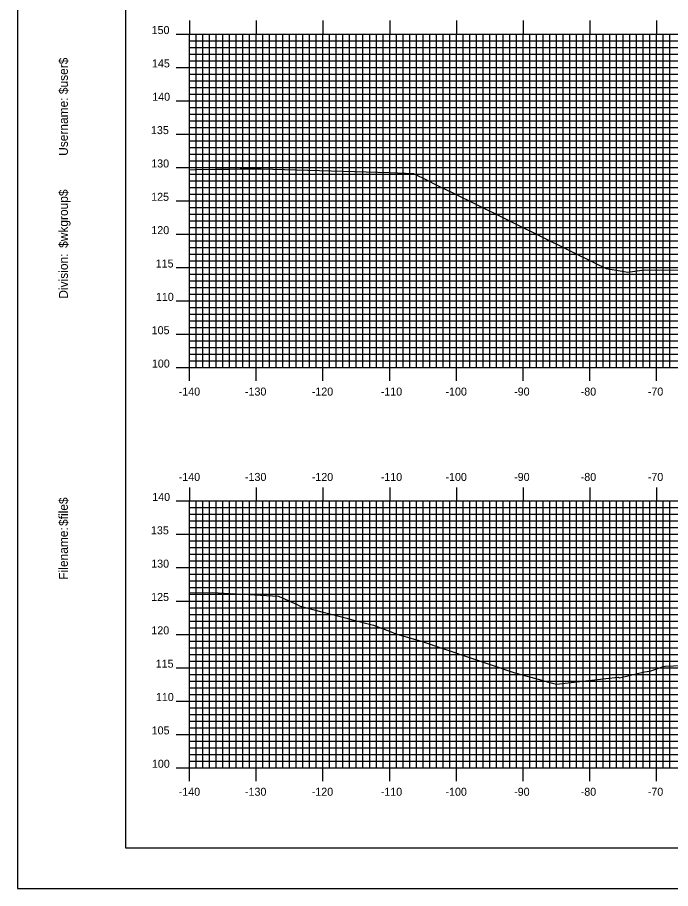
# Model space of a CAD drawing. Extents: x 1684799 to 1685142, y 461260 to 461480.
# Drawn here: x 1684798.9 to 1684896.8, y 461260 to 461390.6 of the extents above; entities that cross this region are included whole.
import ezdxf

# ---------------------------------------------------------------- set-up
doc = ezdxf.new("R2010")
doc.units = 0
for name, color, linetype in [('BORDER', 7, 'Continuous'), ('H_V ANNOTATION', 7, 'Continuous'), ('MAJOR', 7, 'Continuous'), ('MINOR', 7, 'Continuous'), ('PLOT BOUNDARY', 7, 'Continuous'), ('S_Roadway_Centerline', 7, 'Continuous')]:
    doc.layers.add(name, color=color, linetype=linetype)

msp = doc.modelspace()

# ---------------------------------------------------------------- linework, layer by layer
at = {"layer": 'BORDER'}
msp.add_lwpolyline([(1684815.12, 461266.07), (1685135.12, 461266.07), (1685135.12, 461476.07), (1684815.12, 461476.07)], close=True, dxfattribs=at)
at = {"layer": 'MAJOR'}
for p, q in [((1684824.72, 461390.08), (1684824.72, 461388.07)), ((1684834.72, 461390.08), (1684834.72, 461388.07)), ((1684844.72, 461390.08), (1684844.72, 461388.07)), ((1684854.72, 461390.08), (1684854.72, 461388.07)), ((1684864.72, 461390.08), (1684864.72, 461388.07)), ((1684874.72, 461390.08), (1684874.72, 461388.07)), ((1684884.72, 461390.08), (1684884.72, 461388.07)), ((1684894.72, 461390.08), (1684894.72, 461388.07)), ((1684822.71, 461388.07), (1684824.72, 461388.07)), ((1684824.72, 461388.07), (1685104.72, 461388.07)), ((1684824.72, 461338.07), (1684824.72, 461388.07)), ((1684824.72, 461338.07), (1684824.72, 461388.07)), ((1684824.72, 461388.07), (1685104.72, 461388.07)), ((1684834.72, 461338.07), (1684834.72, 461388.07)), ((1684844.72, 461338.07), (1684844.72, 461388.07)), ((1684854.72, 461338.07), (1684854.72, 461388.07)), ((1684864.72, 461338.07), (1684864.72, 461388.07)), ((1684874.72, 461338.07), (1684874.72, 461388.07)), ((1684884.72, 461338.07), (1684884.72, 461388.07)), ((1684894.72, 461338.07), (1684894.72, 461388.07)), ((1684822.71, 461383.07), (1684824.72, 461383.07)), ((1684824.72, 461383.07), (1685104.72, 461383.07)), ((1684822.71, 461378.07), (1684824.72, 461378.07)), ((1684824.72, 461378.07), (1685104.72, 461378.07)), ((1684822.71, 461373.07), (1684824.72, 461373.07)), ((1684824.72, 461373.07), (1685104.72, 461373.07)), ((1684822.71, 461368.07), (1684824.72, 461368.07)), ((1684824.72, 461368.07), (1685104.72, 461368.07)), ((1684822.71, 461363.07), (1684824.72, 461363.07)), ((1684824.72, 461363.07), (1685104.72, 461363.07)), ((1684822.71, 461358.07), (1684824.72, 461358.07)), ((1684824.72, 461358.07), (1685104.72, 461358.07)), ((1684822.71, 461353.07), (1684824.72, 461353.07)), ((1684824.72, 461353.07), (1685104.72, 461353.07)), ((1684822.71, 461348.07), (1684824.72, 461348.07)), ((1684824.72, 461348.07), (1685104.72, 461348.07)), ((1684822.71, 461343.07), (1684824.72, 461343.07)), ((1684824.72, 461343.07), (1685104.72, 461343.07)), ((1684822.71, 461338.07), (1684824.72, 461338.07)), ((1684824.72, 461338.07), (1685104.72, 461338.07)), ((1684824.72, 461338.07), (1685104.72, 461338.07)), ((1684824.72, 461336.07), (1684824.72, 461338.07)), ((1684834.72, 461336.07), (1684834.72, 461338.07)), ((1684844.72, 461336.07), (1684844.72, 461338.07)), ((1684854.72, 461336.07), (1684854.72, 461338.07)), ((1684864.72, 461336.07), (1684864.72, 461338.07)), ((1684874.72, 461336.07), (1684874.72, 461338.07)), ((1684884.72, 461336.07), (1684884.72, 461338.07)), ((1684894.72, 461336.07), (1684894.72, 461338.07)), ((1684824.72, 461320.08), (1684824.72, 461318.07)), ((1684834.72, 461320.08), (1684834.72, 461318.07)), ((1684844.72, 461320.08), (1684844.72, 461318.07)), ((1684854.72, 461320.08), (1684854.72, 461318.07)), ((1684864.72, 461320.08), (1684864.72, 461318.07)), ((1684874.72, 461320.08), (1684874.72, 461318.07)), ((1684884.72, 461320.08), (1684884.72, 461318.07)), ((1684894.72, 461320.08), (1684894.72, 461318.07)), ((1684822.71, 461318.07), (1684824.72, 461318.07)), ((1684824.72, 461318.07), (1685104.72, 461318.07)), ((1684824.72, 461278.07), (1684824.72, 461318.07)), ((1684824.72, 461278.07), (1684824.72, 461318.07)), ((1684824.72, 461318.07), (1685104.72, 461318.07)), ((1684834.72, 461278.07), (1684834.72, 461318.07)), ((1684844.72, 461278.07), (1684844.72, 461318.07)), ((1684854.72, 461278.07), (1684854.72, 461318.07)), ((1684864.72, 461278.07), (1684864.72, 461318.07)), ((1684874.72, 461278.07), (1684874.72, 461318.07)), ((1684884.72, 461278.07), (1684884.72, 461318.07)), ((1684894.72, 461278.07), (1684894.72, 461318.07)), ((1684822.71, 461313.07), (1684824.72, 461313.07)), ((1684824.72, 461313.07), (1685104.72, 461313.07)), ((1684822.71, 461308.07), (1684824.72, 461308.07)), ((1684824.72, 461308.07), (1685104.72, 461308.07)), ((1684822.71, 461303.07), (1684824.72, 461303.07)), ((1684824.72, 461303.07), (1685104.72, 461303.07)), ((1684822.71, 461298.07), (1684824.72, 461298.07)), ((1684824.72, 461298.07), (1685104.72, 461298.07)), ((1684822.71, 461293.07), (1684824.72, 461293.07)), ((1684824.72, 461293.07), (1685104.72, 461293.07)), ((1684822.71, 461288.07), (1684824.72, 461288.07)), ((1684824.72, 461288.07), (1685104.72, 461288.07)), ((1684822.71, 461283.07), (1684824.72, 461283.07)), ((1684824.72, 461283.07), (1685104.72, 461283.07)), ((1684822.71, 461278.07), (1684824.72, 461278.07)), ((1684824.72, 461278.07), (1685104.72, 461278.07)), ((1684824.72, 461278.07), (1685104.72, 461278.07)), ((1684824.72, 461276.07), (1684824.72, 461278.07)), ((1684834.72, 461276.07), (1684834.72, 461278.07)), ((1684844.72, 461276.07), (1684844.72, 461278.07)), ((1684854.72, 461276.07), (1684854.72, 461278.07)), ((1684864.72, 461276.07), (1684864.72, 461278.07)), ((1684874.72, 461276.07), (1684874.72, 461278.07)), ((1684884.72, 461276.07), (1684884.72, 461278.07)), ((1684894.72, 461276.07), (1684894.72, 461278.07))]:
    msp.add_line(p, q, dxfattribs=at)
at = {"layer": 'MINOR'}
for p, q in [((1684825.72, 461338.07), (1684825.72, 461388.07)), ((1684826.72, 461338.07), (1684826.72, 461388.07)), ((1684827.72, 461338.07), (1684827.72, 461388.07)), ((1684828.72, 461338.07), (1684828.72, 461388.07)), ((1684829.72, 461338.07), (1684829.72, 461388.07)), ((1684830.72, 461338.07), (1684830.72, 461388.07)), ((1684831.72, 461338.07), (1684831.72, 461388.07)), ((1684832.72, 461338.07), (1684832.72, 461388.07)), ((1684833.72, 461338.07), (1684833.72, 461388.07)), ((1684835.72, 461338.07), (1684835.72, 461388.07)), ((1684836.72, 461338.07), (1684836.72, 461388.07)), ((1684837.72, 461338.07), (1684837.72, 461388.07)), ((1684838.72, 461338.07), (1684838.72, 461388.07)), ((1684839.72, 461338.07), (1684839.72, 461388.07)), ((1684840.72, 461338.07), (1684840.72, 461388.07)), ((1684841.72, 461338.07), (1684841.72, 461388.07)), ((1684842.72, 461338.07), (1684842.72, 461388.07)), ((1684843.72, 461338.07), (1684843.72, 461388.07)), ((1684845.72, 461338.07), (1684845.72, 461388.07)), ((1684846.72, 461338.07), (1684846.72, 461388.07)), ((1684847.72, 461338.07), (1684847.72, 461388.07)), ((1684848.72, 461338.07), (1684848.72, 461388.07)), ((1684849.72, 461338.07), (1684849.72, 461388.07)), ((1684850.72, 461338.07), (1684850.72, 461388.07)), ((1684851.72, 461338.07), (1684851.72, 461388.07)), ((1684852.72, 461338.07), (1684852.72, 461388.07)), ((1684853.72, 461338.07), (1684853.72, 461388.07)), ((1684855.72, 461338.07), (1684855.72, 461388.07)), ((1684856.72, 461338.07), (1684856.72, 461388.07)), ((1684857.72, 461338.07), (1684857.72, 461388.07)), ((1684858.72, 461338.07), (1684858.72, 461388.07)), ((1684859.72, 461338.07), (1684859.72, 461388.07)), ((1684860.72, 461338.07), (1684860.72, 461388.07)), ((1684861.72, 461338.07), (1684861.72, 461388.07)), ((1684862.72, 461338.07), (1684862.72, 461388.07)), ((1684863.72, 461338.07), (1684863.72, 461388.07)), ((1684865.72, 461338.07), (1684865.72, 461388.07)), ((1684866.72, 461338.07), (1684866.72, 461388.07)), ((1684867.72, 461338.07), (1684867.72, 461388.07)), ((1684868.72, 461338.07), (1684868.72, 461388.07)), ((1684869.72, 461338.07), (1684869.72, 461388.07)), ((1684870.72, 461338.07), (1684870.72, 461388.07)), ((1684871.72, 461338.07), (1684871.72, 461388.07)), ((1684872.72, 461338.07), (1684872.72, 461388.07)), ((1684873.72, 461338.07), (1684873.72, 461388.07)), ((1684875.72, 461338.07), (1684875.72, 461388.07)), ((1684876.72, 461338.07), (1684876.72, 461388.07)), ((1684877.72, 461338.07), (1684877.72, 461388.07)), ((1684878.72, 461338.07), (1684878.72, 461388.07)), ((1684879.72, 461338.07), (1684879.72, 461388.07)), ((1684880.72, 461338.07), (1684880.72, 461388.07)), ((1684881.72, 461338.07), (1684881.72, 461388.07)), ((1684882.72, 461338.07), (1684882.72, 461388.07)), ((1684883.72, 461338.07), (1684883.72, 461388.07)), ((1684885.72, 461338.07), (1684885.72, 461388.07)), ((1684886.72, 461338.07), (1684886.72, 461388.07)), ((1684887.72, 461338.07), (1684887.72, 461388.07)), ((1684888.72, 461338.07), (1684888.72, 461388.07)), ((1684889.72, 461338.07), (1684889.72, 461388.07)), ((1684890.72, 461338.07), (1684890.72, 461388.07)), ((1684891.72, 461338.07), (1684891.72, 461388.07)), ((1684892.72, 461338.07), (1684892.72, 461388.07)), ((1684893.72, 461338.07), (1684893.72, 461388.07)), ((1684895.72, 461338.07), (1684895.72, 461388.07)), ((1684896.72, 461338.07), (1684896.72, 461388.07)), ((1684824.72, 461387.07), (1685104.72, 461387.07)), ((1684824.72, 461387.07), (1684826.72, 461387.07)), ((1684824.72, 461386.07), (1685104.72, 461386.07)), ((1684824.72, 461386.07), (1684826.72, 461386.07)), ((1684824.72, 461385.07), (1685104.72, 461385.07)), ((1684824.72, 461385.07), (1684826.72, 461385.07)), ((1684824.72, 461384.07), (1685104.72, 461384.07)), ((1684824.72, 461384.07), (1684826.72, 461384.07)), ((1684824.72, 461382.07), (1685104.72, 461382.07)), ((1684824.72, 461382.07), (1684826.72, 461382.07)), ((1684824.72, 461381.07), (1685104.72, 461381.07)), ((1684824.72, 461381.07), (1684826.72, 461381.07)), ((1684824.72, 461380.07), (1685104.72, 461380.07)), ((1684824.72, 461380.07), (1684826.72, 461380.07)), ((1684824.72, 461379.07), (1685104.72, 461379.07)), ((1684824.72, 461379.07), (1684826.72, 461379.07)), ((1684824.72, 461377.07), (1685104.72, 461377.07)), ((1684824.72, 461377.07), (1684826.72, 461377.07)), ((1684824.72, 461376.07), (1685104.72, 461376.07)), ((1684824.72, 461376.07), (1684826.72, 461376.07)), ((1684824.72, 461375.07), (1685104.72, 461375.07)), ((1684824.72, 461375.07), (1684826.72, 461375.07)), ((1684824.72, 461374.07), (1685104.72, 461374.07)), ((1684824.72, 461374.07), (1684826.72, 461374.07)), ((1684824.72, 461372.07), (1685104.72, 461372.07)), ((1684824.72, 461372.07), (1684826.72, 461372.07)), ((1684824.72, 461371.07), (1685104.72, 461371.07)), ((1684824.72, 461371.07), (1684826.72, 461371.07)), ((1684824.72, 461370.07), (1685104.72, 461370.07)), ((1684824.72, 461370.07), (1684826.72, 461370.07)), ((1684824.72, 461369.07), (1685104.72, 461369.07)), ((1684824.72, 461369.07), (1684826.72, 461369.07)), ((1684824.72, 461367.07), (1685104.72, 461367.07)), ((1684824.72, 461367.07), (1684826.72, 461367.07)), ((1684824.72, 461366.07), (1685104.72, 461366.07)), ((1684824.72, 461366.07), (1684826.72, 461366.07)), ((1684824.72, 461365.07), (1685104.72, 461365.07)), ((1684824.72, 461365.07), (1684826.72, 461365.07)), ((1684824.72, 461364.07), (1685104.72, 461364.07)), ((1684824.72, 461364.07), (1684826.72, 461364.07)), ((1684824.72, 461362.07), (1685104.72, 461362.07)), ((1684824.72, 461362.07), (1684826.72, 461362.07)), ((1684824.72, 461361.07), (1685104.72, 461361.07)), ((1684824.72, 461361.07), (1684826.72, 461361.07)), ((1684824.72, 461360.07), (1685104.72, 461360.07)), ((1684824.72, 461360.07), (1684826.72, 461360.07)), ((1684824.72, 461359.07), (1685104.72, 461359.07)), ((1684824.72, 461359.07), (1684826.72, 461359.07)), ((1684824.72, 461357.07), (1685104.72, 461357.07)), ((1684824.72, 461357.07), (1684826.72, 461357.07)), ((1684824.72, 461356.07), (1685104.72, 461356.07)), ((1684824.72, 461356.07), (1684826.72, 461356.07)), ((1684824.72, 461355.07), (1685104.72, 461355.07)), ((1684824.72, 461355.07), (1684826.72, 461355.07)), ((1684824.72, 461354.07), (1685104.72, 461354.07)), ((1684824.72, 461354.07), (1684826.72, 461354.07)), ((1684824.72, 461352.07), (1685104.72, 461352.07)), ((1684824.72, 461352.07), (1684826.72, 461352.07)), ((1684824.72, 461351.07), (1685104.72, 461351.07)), ((1684824.72, 461351.07), (1684826.72, 461351.07)), ((1684824.72, 461350.07), (1685104.72, 461350.07)), ((1684824.72, 461350.07), (1684826.72, 461350.07)), ((1684824.72, 461349.07), (1685104.72, 461349.07)), ((1684824.72, 461349.07), (1684826.72, 461349.07)), ((1684824.72, 461347.07), (1685104.72, 461347.07)), ((1684824.72, 461347.07), (1684826.72, 461347.07)), ((1684824.72, 461346.07), (1685104.72, 461346.07)), ((1684824.72, 461346.07), (1684826.72, 461346.07)), ((1684824.72, 461345.07), (1685104.72, 461345.07)), ((1684824.72, 461345.07), (1684826.72, 461345.07)), ((1684824.72, 461344.07), (1685104.72, 461344.07)), ((1684824.72, 461344.07), (1684826.72, 461344.07)), ((1684824.72, 461342.07), (1685104.72, 461342.07)), ((1684824.72, 461342.07), (1684826.72, 461342.07)), ((1684824.72, 461341.07), (1685104.72, 461341.07)), ((1684824.72, 461341.07), (1684826.72, 461341.07)), ((1684824.72, 461340.07), (1685104.72, 461340.07)), ((1684824.72, 461340.07), (1684826.72, 461340.07)), ((1684824.72, 461339.07), (1685104.72, 461339.07)), ((1684824.72, 461339.07), (1684826.72, 461339.07)), ((1684824.72, 461317.07), (1685104.72, 461317.07)), ((1684824.72, 461317.07), (1684826.72, 461317.07)), ((1684825.72, 461278.07), (1684825.72, 461318.07)), ((1684826.72, 461278.07), (1684826.72, 461318.07)), ((1684827.72, 461278.07), (1684827.72, 461318.07)), ((1684828.72, 461278.07), (1684828.72, 461318.07)), ((1684829.72, 461278.07), (1684829.72, 461318.07)), ((1684830.72, 461278.07), (1684830.72, 461318.07)), ((1684831.72, 461278.07), (1684831.72, 461318.07)), ((1684832.72, 461278.07), (1684832.72, 461318.07)), ((1684833.72, 461278.07), (1684833.72, 461318.07)), ((1684835.72, 461278.07), (1684835.72, 461318.07)), ((1684836.72, 461278.07), (1684836.72, 461318.07)), ((1684837.72, 461278.07), (1684837.72, 461318.07)), ((1684838.72, 461278.07), (1684838.72, 461318.07)), ((1684839.72, 461278.07), (1684839.72, 461318.07)), ((1684840.72, 461278.07), (1684840.72, 461318.07)), ((1684841.72, 461278.07), (1684841.72, 461318.07)), ((1684842.72, 461278.07), (1684842.72, 461318.07)), ((1684843.72, 461278.07), (1684843.72, 461318.07)), ((1684845.72, 461278.07), (1684845.72, 461318.07)), ((1684846.72, 461278.07), (1684846.72, 461318.07)), ((1684847.72, 461278.07), (1684847.72, 461318.07)), ((1684848.72, 461278.07), (1684848.72, 461318.07)), ((1684849.72, 461278.07), (1684849.72, 461318.07)), ((1684850.72, 461278.07), (1684850.72, 461318.07)), ((1684851.72, 461278.07), (1684851.72, 461318.07)), ((1684852.72, 461278.07), (1684852.72, 461318.07)), ((1684853.72, 461278.07), (1684853.72, 461318.07)), ((1684855.72, 461278.07), (1684855.72, 461318.07)), ((1684856.72, 461278.07), (1684856.72, 461318.07)), ((1684857.72, 461278.07), (1684857.72, 461318.07)), ((1684858.72, 461278.07), (1684858.72, 461318.07)), ((1684859.72, 461278.07), (1684859.72, 461318.07)), ((1684860.72, 461278.07), (1684860.72, 461318.07)), ((1684861.72, 461278.07), (1684861.72, 461318.07)), ((1684862.72, 461278.07), (1684862.72, 461318.07)), ((1684863.72, 461278.07), (1684863.72, 461318.07)), ((1684865.72, 461278.07), (1684865.72, 461318.07)), ((1684866.72, 461278.07), (1684866.72, 461318.07)), ((1684867.72, 461278.07), (1684867.72, 461318.07)), ((1684868.72, 461278.07), (1684868.72, 461318.07)), ((1684869.72, 461278.07), (1684869.72, 461318.07)), ((1684870.72, 461278.07), (1684870.72, 461318.07)), ((1684871.72, 461278.07), (1684871.72, 461318.07)), ((1684872.72, 461278.07), (1684872.72, 461318.07)), ((1684873.72, 461278.07), (1684873.72, 461318.07)), ((1684875.72, 461278.07), (1684875.72, 461318.07)), ((1684876.72, 461278.07), (1684876.72, 461318.07)), ((1684877.72, 461278.07), (1684877.72, 461318.07)), ((1684878.72, 461278.07), (1684878.72, 461318.07)), ((1684879.72, 461278.07), (1684879.72, 461318.07)), ((1684880.72, 461278.07), (1684880.72, 461318.07)), ((1684881.72, 461278.07), (1684881.72, 461318.07)), ((1684882.72, 461278.07), (1684882.72, 461318.07)), ((1684883.72, 461278.07), (1684883.72, 461318.07)), ((1684885.72, 461278.07), (1684885.72, 461318.07)), ((1684886.72, 461278.07), (1684886.72, 461318.07)), ((1684887.72, 461278.07), (1684887.72, 461318.07)), ((1684888.72, 461278.07), (1684888.72, 461318.07)), ((1684889.72, 461278.07), (1684889.72, 461318.07)), ((1684890.72, 461278.07), (1684890.72, 461318.07)), ((1684891.72, 461278.07), (1684891.72, 461318.07)), ((1684892.72, 461278.07), (1684892.72, 461318.07)), ((1684893.72, 461278.07), (1684893.72, 461318.07)), ((1684895.72, 461278.07), (1684895.72, 461318.07)), ((1684896.72, 461278.07), (1684896.72, 461318.07)), ((1684824.72, 461316.07), (1685104.72, 461316.07)), ((1684824.72, 461316.07), (1684826.72, 461316.07)), ((1684824.72, 461315.07), (1685104.72, 461315.07)), ((1684824.72, 461315.07), (1684826.72, 461315.07)), ((1684824.72, 461314.07), (1685104.72, 461314.07)), ((1684824.72, 461314.07), (1684826.72, 461314.07)), ((1684824.72, 461312.07), (1685104.72, 461312.07)), ((1684824.72, 461312.07), (1684826.72, 461312.07)), ((1684824.72, 461311.07), (1685104.72, 461311.07)), ((1684824.72, 461311.07), (1684826.72, 461311.07)), ((1684824.72, 461310.07), (1685104.72, 461310.07)), ((1684824.72, 461310.07), (1684826.72, 461310.07)), ((1684824.72, 461309.07), (1685104.72, 461309.07)), ((1684824.72, 461309.07), (1684826.72, 461309.07)), ((1684824.72, 461307.07), (1685104.72, 461307.07)), ((1684824.72, 461307.07), (1684826.72, 461307.07)), ((1684824.72, 461306.07), (1685104.72, 461306.07)), ((1684824.72, 461306.07), (1684826.72, 461306.07)), ((1684824.72, 461305.07), (1685104.72, 461305.07)), ((1684824.72, 461305.07), (1684826.72, 461305.07)), ((1684824.72, 461304.07), (1685104.72, 461304.07)), ((1684824.72, 461304.07), (1684826.72, 461304.07)), ((1684824.72, 461302.07), (1685104.72, 461302.07)), ((1684824.72, 461302.07), (1684826.72, 461302.07)), ((1684824.72, 461301.07), (1685104.72, 461301.07)), ((1684824.72, 461301.07), (1684826.72, 461301.07)), ((1684824.72, 461300.07), (1685104.72, 461300.07)), ((1684824.72, 461300.07), (1684826.72, 461300.07)), ((1684824.72, 461299.07), (1685104.72, 461299.07)), ((1684824.72, 461299.07), (1684826.72, 461299.07)), ((1684824.72, 461297.07), (1685104.72, 461297.07)), ((1684824.72, 461297.07), (1684826.72, 461297.07)), ((1684824.72, 461296.07), (1685104.72, 461296.07)), ((1684824.72, 461296.07), (1684826.72, 461296.07)), ((1684824.72, 461295.07), (1685104.72, 461295.07)), ((1684824.72, 461295.07), (1684826.72, 461295.07)), ((1684824.72, 461294.07), (1685104.72, 461294.07)), ((1684824.72, 461294.07), (1684826.72, 461294.07)), ((1684824.72, 461292.07), (1685104.72, 461292.07)), ((1684824.72, 461292.07), (1684826.72, 461292.07)), ((1684824.72, 461291.07), (1685104.72, 461291.07)), ((1684824.72, 461291.07), (1684826.72, 461291.07)), ((1684824.72, 461290.07), (1685104.72, 461290.07)), ((1684824.72, 461290.07), (1684826.72, 461290.07)), ((1684824.72, 461289.07), (1685104.72, 461289.07)), ((1684824.72, 461289.07), (1684826.72, 461289.07)), ((1684824.72, 461287.07), (1685104.72, 461287.07)), ((1684824.72, 461287.07), (1684826.72, 461287.07)), ((1684824.72, 461286.07), (1685104.72, 461286.07)), ((1684824.72, 461286.07), (1684826.72, 461286.07)), ((1684824.72, 461285.07), (1685104.72, 461285.07)), ((1684824.72, 461285.07), (1684826.72, 461285.07)), ((1684824.72, 461284.07), (1685104.72, 461284.07)), ((1684824.72, 461284.07), (1684826.72, 461284.07)), ((1684824.72, 461282.07), (1685104.72, 461282.07)), ((1684824.72, 461282.07), (1684826.72, 461282.07)), ((1684824.72, 461281.07), (1685104.72, 461281.07)), ((1684824.72, 461281.07), (1684826.72, 461281.07)), ((1684824.72, 461280.07), (1685104.72, 461280.07)), ((1684824.72, 461280.07), (1684826.72, 461280.07)), ((1684824.72, 461279.07), (1685104.72, 461279.07)), ((1684824.72, 461279.07), (1684826.72, 461279.07))]:
    msp.add_line(p, q, dxfattribs=at)
at = {"layer": 'PLOT BOUNDARY'}
msp.add_lwpolyline([(1684798.93, 461259.95), (1685138.93, 461259.95), (1685138.93, 461479.95), (1684798.93, 461479.95)], close=True, dxfattribs=at)
at = {"layer": 'S_Roadway_Centerline'}
for points in [[(1684824.72, 461367.73), (1684825.59, 461367.74), (1684828.78, 461367.82), (1684830.6, 461367.83), (1684832.31, 461367.84), (1684833.93, 461367.85), (1684835.46, 461367.86), (1684854.71, 461367.32), (1684858.3, 461367.17), (1684859.07, 461366.79), (1684859.56, 461366.55), (1684862.51, 461365.09), (1684864.08, 461364.31), (1684871.76, 461360.52), (1684873.59, 461359.61), (1684885.52, 461353.72), (1684885.52, 461353.72), (1684887.16, 461352.91)], [(1684887.15, 461352.91), (1684889.85, 461352.47), (1684890.43, 461352.39), (1684891.12, 461352.48), (1684892.87, 461352.73), (1684895.77, 461352.69), (1684899.59, 461352.72)], [(1684824.72, 461304.31), (1684828.11, 461304.32), (1684838.08, 461303.8)], [(1684838.08, 461303.8), (1684840.5, 461302.71), (1684840.76, 461302.59), (1684841.28, 461302.29), (1684844.37, 461301.5), (1684844.76, 461301.4), (1684848.29, 461300.49), (1684848.96, 461300.32), (1684852.27, 461299.47), (1684854.69, 461298.57), (1684855.63, 461298.14), (1684859.42, 461297.05), (1684873.48, 461292.29), (1684877.52, 461291.21), (1684878.33, 461290.96), (1684879.72, 461290.62)], [(1684879.72, 461290.62), (1684886.77, 461291.38), (1684887.13, 461291.44), (1684888.96, 461291.65), (1684889.17, 461291.56), (1684892.92, 461292.46), (1684893.71, 461292.57), (1684895.77, 461293.25), (1684895.99, 461293.28), (1684902.32, 461293.53)]]:
    msp.add_lwpolyline(points, dxfattribs=at)

# ---------------------------------------------------------------- texts
at = {"layer": 'BORDER'}
for s, p in [('$user$', (1684806.49, 461379.06)), ('Username:', (1684806.49, 461369.81)), ('$wkgroup$', (1684806.49, 461356.01)), ('Division:', (1684806.49, 461348.4)), ('$file$', (1684806.49, 461314.32)), ('Filename:', (1684806.49, 461306.27))]:
    msp.add_text(s, height=1.339, rotation=90, dxfattribs=at).set_placement(p)
at = {"layer": 'H_V ANNOTATION'}
for s, p in [('150', (1684819.04, 461388.07)), ('145', (1684819.09, 461383.07)), ('140', (1684819.13, 461378.07)), ('135', (1684818.94, 461373.07)), ('130', (1684818.98, 461368.07)), ('125', (1684818.97, 461363.07)), ('120', (1684819, 461358.07)), ('115', (1684819.65, 461353.07)), ('110', (1684819.68, 461348.07)), ('105', (1684819.05, 461343.07)), ('100', (1684819.08, 461338.07)), ('-140', (1684823.1, 461333.87)), ('-130', (1684833.03, 461333.87)), ('-120', (1684843.04, 461333.87)), ('-110', (1684853.38, 461333.87)), ('-100', (1684863.08, 461333.87)), ('-90', (1684873.37, 461333.87)), ('-80', (1684883.35, 461333.87)), ('-70', (1684893.4, 461333.87)), ('-140', (1684823.1, 461321.07)), ('-130', (1684833.03, 461321.07)), ('-120', (1684843.04, 461321.07)), ('-110', (1684853.38, 461321.07)), ('-100', (1684863.08, 461321.07)), ('-90', (1684873.37, 461321.07)), ('-80', (1684883.35, 461321.07)), ('-70', (1684893.4, 461321.07)), ('140', (1684819.13, 461318.07)), ('135', (1684818.94, 461313.07)), ('130', (1684818.98, 461308.07)), ('125', (1684818.97, 461303.07)), ('120', (1684819, 461298.07)), ('115', (1684819.65, 461293.07)), ('110', (1684819.68, 461288.07)), ('105', (1684819.05, 461283.07)), ('100', (1684819.08, 461278.07)), ('-140', (1684823.1, 461273.87)), ('-130', (1684833.03, 461273.87)), ('-120', (1684843.04, 461273.87)), ('-110', (1684853.38, 461273.87)), ('-100', (1684863.08, 461273.87)), ('-90', (1684873.37, 461273.87)), ('-80', (1684883.35, 461273.87)), ('-70', (1684893.4, 461273.87))]:
    msp.add_text(s, height=1.2, dxfattribs=at).set_placement(p)
at = {"layer": 'MAJOR'}
for p in [(1684824.71, 461338.07), (1684824.71, 461278.07)]:
    msp.add_text('-', height=0.012, dxfattribs=at).set_placement(p)

doc.saveas('drawing.dxf')
